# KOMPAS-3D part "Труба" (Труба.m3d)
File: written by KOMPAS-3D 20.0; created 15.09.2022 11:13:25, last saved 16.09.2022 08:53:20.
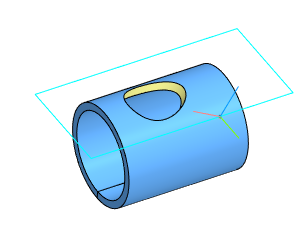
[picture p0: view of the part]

Document properties: Полное имя файла: D:\YAKOVLEV\ПРОЕКТЫ\ДЦ-2. ДП-7 Газопровод Окожушивание\ПРОБА Соединение труб. Окожушивание\ПРОБА 2\Труба.m3d

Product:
- Part/product: Труба
    Материал: Сталь 45  ГОСТ 1050-2013 (density 7810 kg/m3)
    Масса: 15932.7

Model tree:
1. Плоскость под углом:1
     Угол = 30
2. Эскиз:1
3. Обечайка:1
     Расстояние 1 = 2500; Толщина листового тела = 150; Радиус сгиба = 850; Коэффициент = 0.4; Величина сгиба = 10; Зазор = 0.01
4. Эскиз:2  (with: Обечайка:1)
5. Вырез в листовом теле:2
     Глубина выреза = 2220
6. Касательная плоскость:1  (with: Обечайка:1)
7. Развертка  (labels: Сталь 45  ГОСТ 1050-2013)

Expressions: v83*2
Referenced files in D:\YAKOVLEV\ПРОЕКТЫ\ДЦ-2. ДП-7 Газопровод Окожушивание\ПРОБА Соединение труб. Окожушивание\ПРОБА 2\: Соединение труб.a3d
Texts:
  Соединение труб. Окожушивание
